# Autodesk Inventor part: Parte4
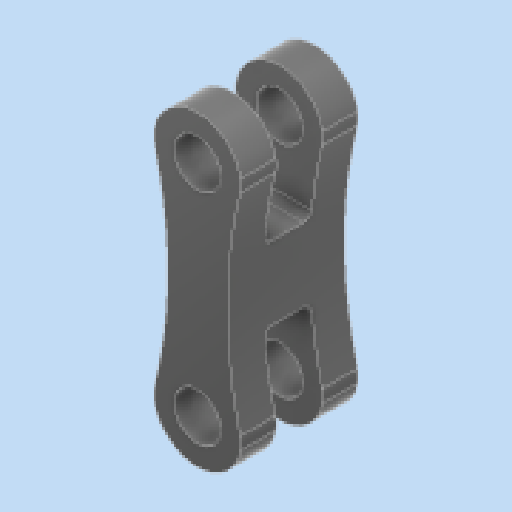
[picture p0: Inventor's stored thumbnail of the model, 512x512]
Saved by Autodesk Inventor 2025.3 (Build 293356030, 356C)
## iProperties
Created: 2026-05
Part Number: Parte4
Material: Generico
Document SubType Name: Modeling
Designer: R5800u
Density: 1 g/cm^3
Appearance: Liscia - Nero
Author: R5800u
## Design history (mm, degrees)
sketch "Schizzo1"
  geometry: L1 (-3, -7.5)-(3, -7.5); L2 (3, -7.5)-(3, 7.5); L3 (3, 7.5)-(-3, 7.5); L4 (-3, 7.5)-(-3, -7.5); L5 (-3, -7.5)-(3, 7.5); L6 (3, -7.5)-(-3, 7.5); 5 further points
  constraints: 12 end point, 4 midpoint, 2 parallel, 1 horizontal, 1 perpendicular, 6 other
  dimensions: "d0" = 6 distance of L3.end L2.end; "d1" = 15 distance of L2.end L1.end
extrude "Estrusione1" new body sketch "Schizzo1" stored distance "d2" = 8; taper "d3" = 0 deg
sketch "Schizzo2"
  geometry: L1 (-3, -7.5)-(-3, 7.5) reference; L2 (3, 7.5)-(3, -7.5) reference; L3 (-3, -2.5)-(3, -2.5); L4 (3, -2.5)-(3, 2.5); L5 (3, 2.5)-(-3, 2.5); L6 (-3, 2.5)-(-3, -2.5); L7 (-3, -2.5)-(3, 2.5); L8 (3, -2.5)-(-3, 2.5); A1 r 3 centre (0, 7.5) between (3, 7.5) and (-3, 7.5) reference; A2 r 3 centre (0, -7.5) between (-3, -7.5) and (3, -7.5) reference; 4 further points
  constraints: 12 end point, 2 midpoint, 2 parallel, 1 horizontal, 1 perpendicular, 1 point on line
  dimensions: "d4" = 5 distance of L4.end L3.end
extrude "Estrusione2" cut sketch "Schizzo2" stored distance "d5" = 3.2; taper "d6" = 0 deg
sketch "Schizzo3"
  geometry: A1 r 3 centre (0, 7.5) between (3, 7.5) and (-3, 7.5) reference; A2 r 3 centre (0, -7.5) between (-3, -7.5) and (3, -7.5) reference; 3 further points
  constraints: 2 coincident
hole "Foro1" sketch "Schizzo3" at (0, 7.5), (0, -7.5) diameter "d7" = 3.2; stored, may be unused: countersink angle "d11" = 90 deg, drill point angle "d13" = 118 deg; dims "d8" = 20, "d9" = 5.5, "d10" = 2.9, "d12" = 26
fillet "Raccordo1" dims "d14" = 0.5
sketch "Schizzo4"
  geometry: L1 (3, -7.5)-(3, 7.5) reference; L2 (-3, -2.866)-(-3, -7.5) reference; L3 (-3, 7.5)-(-3, -7.5) reference; L4 (3, -7.5)-(3, 7.5) reference; C1 r 1.6 at (0, -7.5) reference; C2 r 1.6 at (0, 7.5) reference; A1 r 30 centre (32.047, 0) between (3, 7.5) and (3, -7.5); A2 r 3 centre (0, 7.5) between (3, 7.5) and (-3, 7.5) reference; A3 r 30 centre (-32.047, 0) between (-3, -7.5) and (-3, 7.5); A4 r 3 centre (0, -7.5) between (-3, -7.5) and (3, -7.5) reference; A5 r 3 centre (0, 7.5) between (3, 7.5) and (-3, 7.5) reference; 3 further points
  constraints: 4 point on circle, 2 centre point
  dimensions: "d15" = 30 radius of A1; "d16" = 30 radius of A3
extrude "Estrusione3" cut sketch "Schizzo4" extent not by distance; stored distance "d17" = 0; taper "d18" = 0 deg
fillet "Raccordo2" dims "d19" = 2
node "Solido1"
node "Linea chiusa proiettata1"
node "Linea chiusa proiettata2"
